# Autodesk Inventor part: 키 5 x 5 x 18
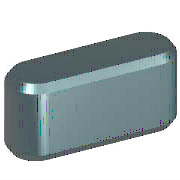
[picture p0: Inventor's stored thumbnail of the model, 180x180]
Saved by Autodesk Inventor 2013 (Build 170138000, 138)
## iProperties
IsCustomPart: 1
Created: 2012-02
Part Number: 키 5 x 5 x 18
Material: 강철, 연강
Description: 키 및 해당 키홈
Document SubType Name: Modeling
Standard: KS B 1311
Designer: mduedu
Standards Organization: KS
Language: ko-KR
Size Designation: 5 x 5 x 18
Categories: <MemberInstance><Categories><Category DisplayName="샤프트 부품" InternalName="7f7aeb1f-a693-4053-b835-cee3144e0d98" Mnemonic="SHFT"><Category DisplayName="키" Interna
Density: 1 g/cm^3
Author: mduedu
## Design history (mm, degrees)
workplane "Work Plane1"
workplane "Work Plane2"
sketch "스케치1"
  geometry: L1 (2.5, 2.5)-(15.5, 2.5); L2 (15.5, -2.5)-(2.5, -2.5); L3 (0, 9.4)-(0, -7.4) reference; L4 (-5, 0)-(30, 0) reference; L5 (18, 0)-(18, 7); A1 r 2.5 centre (2.5, 0) between (2.5, 2.5) and (2.5, -2.5); A2 r 2.5 centre (15.5, 0) between (15.5, -2.5) and (15.5, 2.5)
  constraints: 6 end point, 5 point on circle, 4 tangent, 3 point on line, 2 centre point, 1 horizontal, 1 parallel, 1 perpendicular
  dimensions: "d0" = 2.5 radius of A1 (= 0.5 x PB); "d13" = 2.5 radius of A2 (= 0.5 x PB); "d14" = 18 distance between parallel lines of L5 L3 (= NLG)
extrude "본체1" new body sketch "스케치1" taper "d3" = 0 deg; stored distance "d4" = 10
workplane "Work Plane3"
body "Solid1"
chamfer "모따기1" distance "d8" = 0.4 (= PHH); stored, may be unused: second distance "d9" = 0.4 (= PHH), angle "d15" = 45 deg
other parameters: "d1" = -3 (= -PNT), "d2" = 2 (= PH - PNT), "NLG" = 18 [user parameter; used in 3 equation terms], "PB" = 5 [user parameter; used in 2 equation terms], "PNT" = 3 [user parameter; used in 2 equation terms], "PH" = 5 [user parameter; used in 1 equation term], "PHH" = 0.4 [user parameter; used in 2 equation terms], "d10" = 0, "d16" = 0, "d17" = 0, "d18" = 0, "WDMIN" = 12 [user parameter], "PLB2" = 18 (= NLG) [user parameter], "WDMAX" = 17 [user parameter], "PLB1" = 18 (= NLG) [user parameter], "RR" = 0.16 [user parameter], "PUEB" = 2.3 [user parameter]
